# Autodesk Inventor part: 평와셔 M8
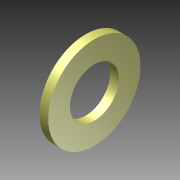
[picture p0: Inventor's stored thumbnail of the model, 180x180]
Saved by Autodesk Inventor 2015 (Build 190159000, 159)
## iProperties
Created: 2024-12
Part Number: 평와셔 M8
Material: 일반
Document SubType Name: Modeling
Designer: 10401
Density: 1 g/cm^3
Appearance: 기본값
Author: 10401
Author: jhkim
Description: 평면 와셔
Creation Date: 2024-11-28
Sending System: Autodesk Inventor 2025
Preprocessor: ST-DEVELOPER v20
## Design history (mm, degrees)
node "평와셔 M81"
body "Solid1"
node "기준1"
